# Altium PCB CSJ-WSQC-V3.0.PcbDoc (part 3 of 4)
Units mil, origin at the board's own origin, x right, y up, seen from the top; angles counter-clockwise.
Board outline 5060 x 7131.55 mil, 4 copper layers (Top Layer, InternalPlane1, InternalPlane2, Bottom Layer); 390 components, 277 nets, 1183 pads, 601 vias.
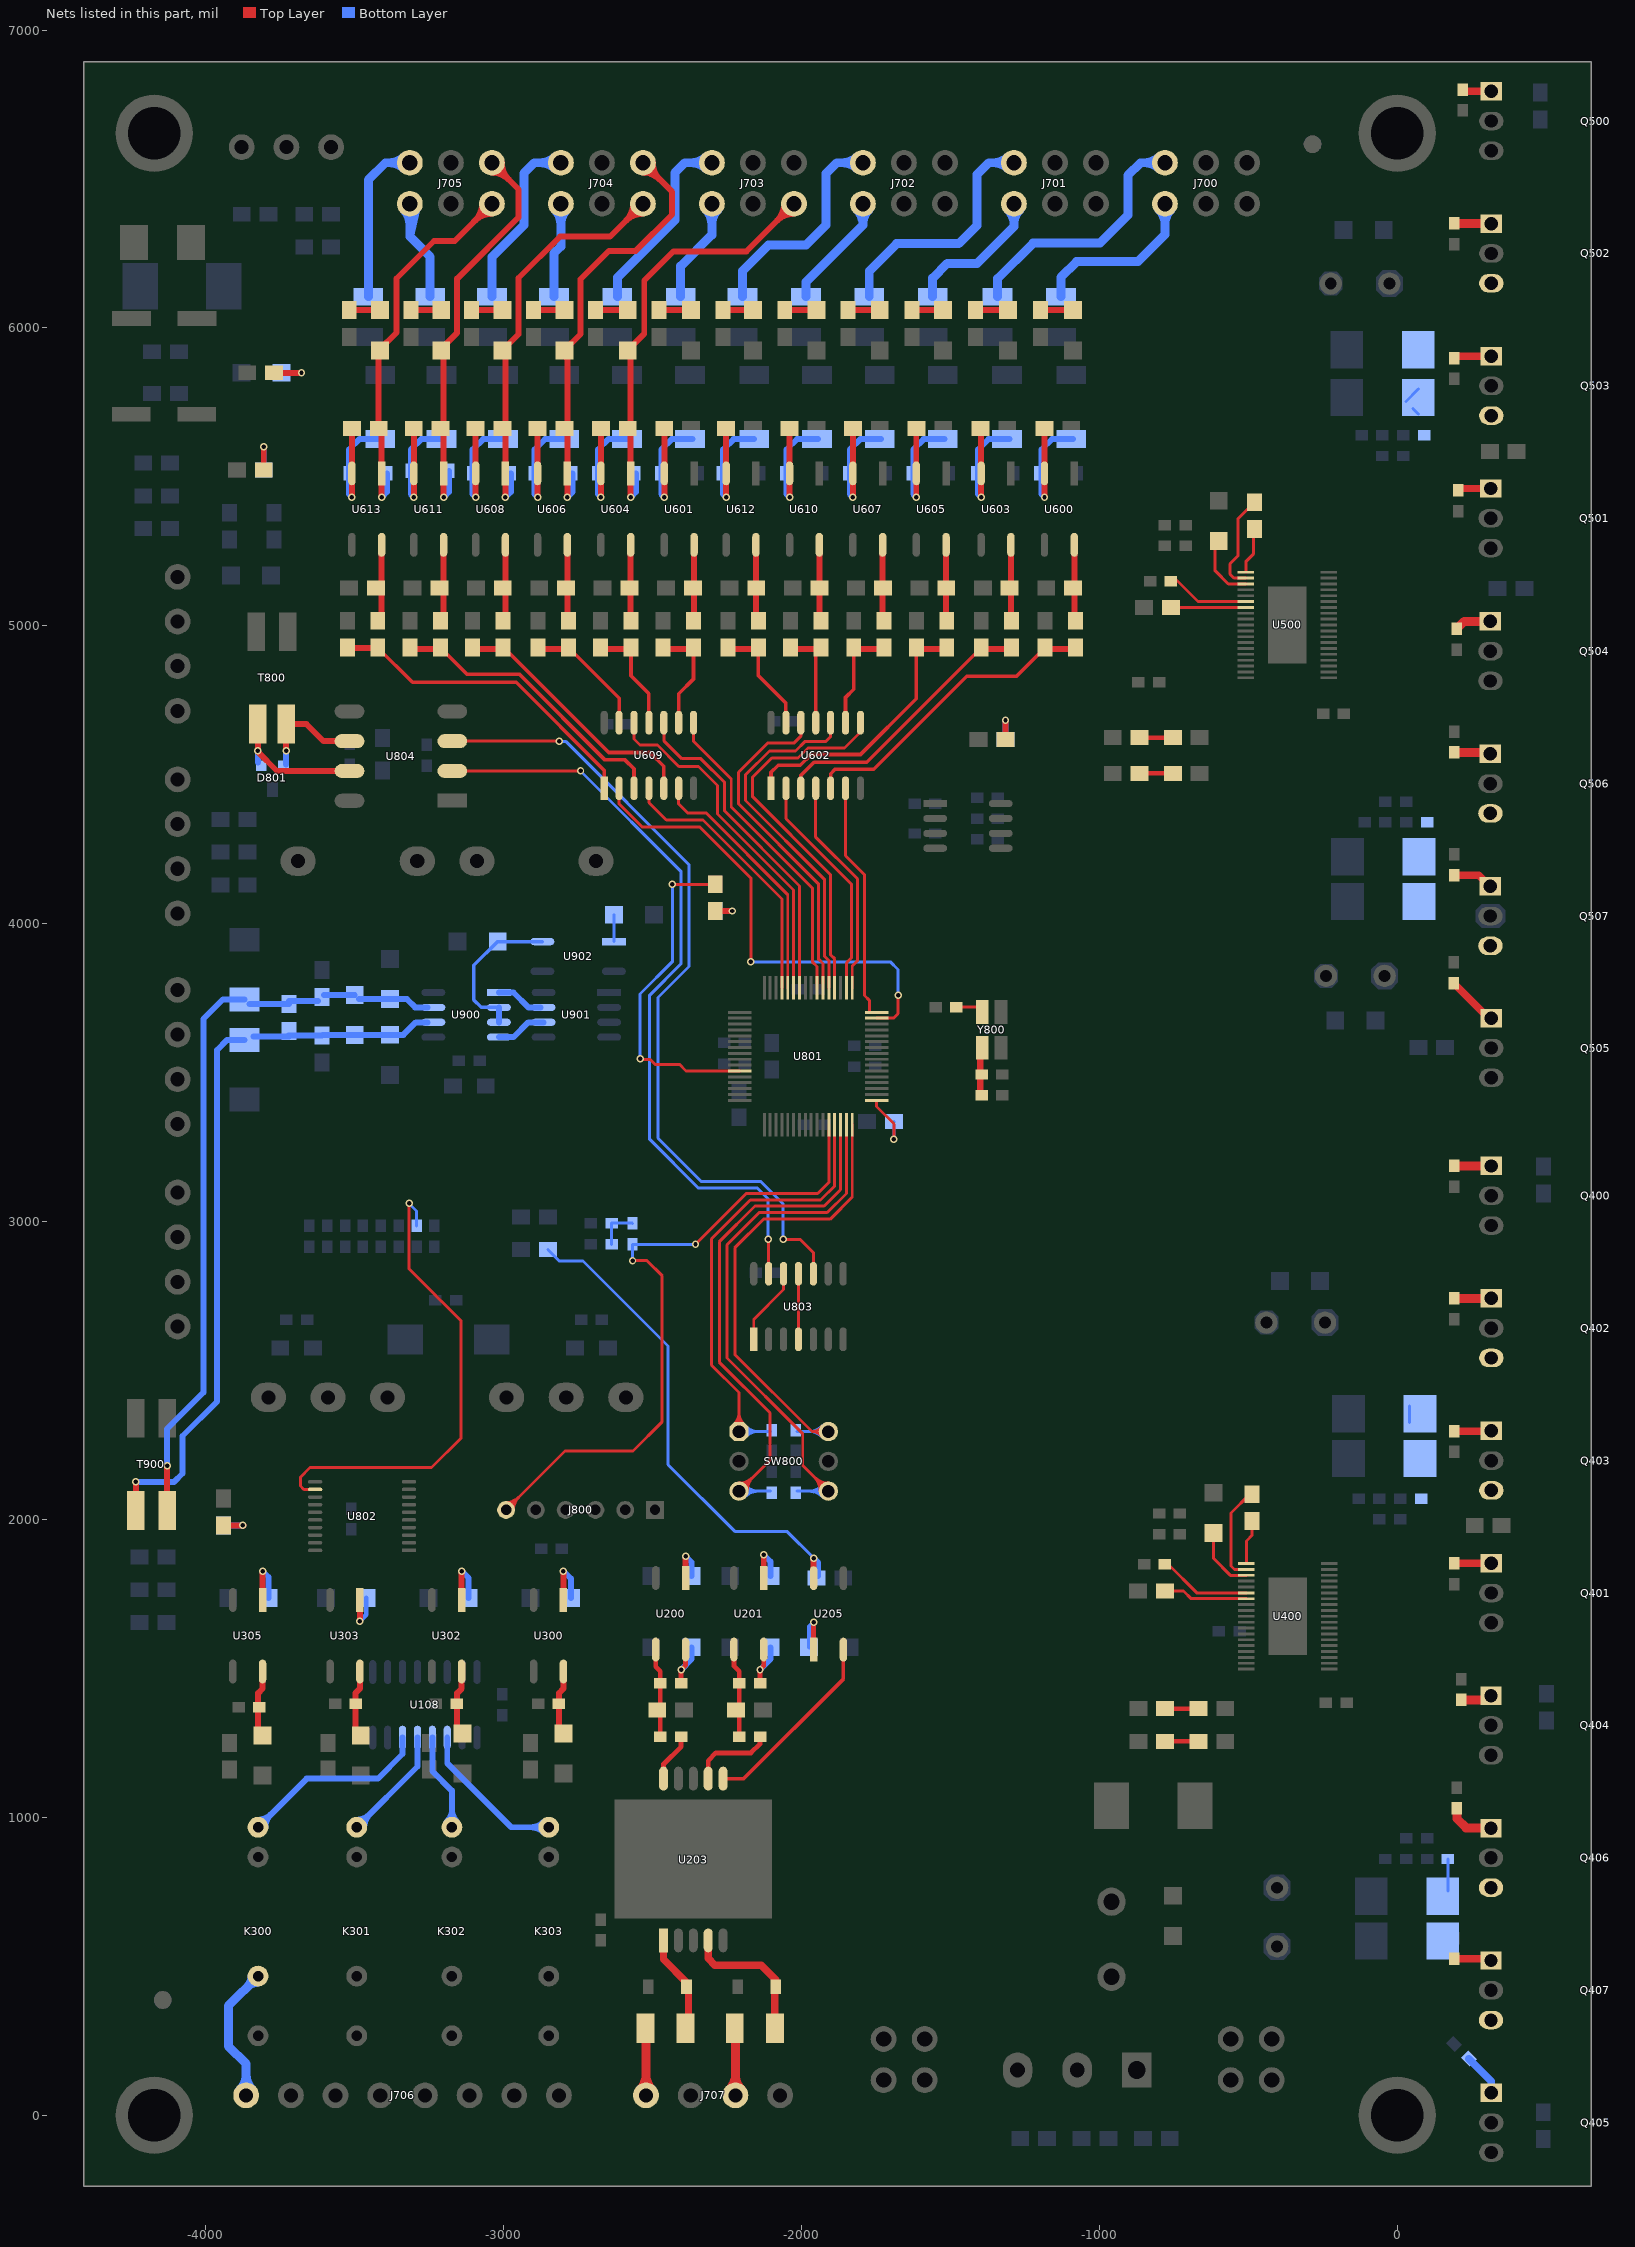
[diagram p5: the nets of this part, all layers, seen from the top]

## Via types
v1: diameter 25, hole 15, Top Layer to Bottom Layer, 303 vias
v2: diameter 25, hole 12, Top Layer to Bottom Layer, 94 vias
v3: diameter 50, hole 25, Top Layer to Bottom Layer, 71 vias
v4: diameter 30, hole 16, Top Layer to Bottom Layer, 71 vias
v5: diameter 12, hole 8, Top Layer to Bottom Layer, 25 vias
v6: diameter 25, hole 12, Top Layer to Bottom Layer, tented both sides, 24 vias
v7: diameter 35, hole 20, Top Layer to Bottom Layer, 7 vias
v8: diameter 20, hole 12, Top Layer to Bottom Layer, 3 vias
v9: diameter 8, hole 5, Top Layer to Bottom Layer, 2 vias
v10: diameter 35, hole 25, Top Layer to Bottom Layer, 1 vias

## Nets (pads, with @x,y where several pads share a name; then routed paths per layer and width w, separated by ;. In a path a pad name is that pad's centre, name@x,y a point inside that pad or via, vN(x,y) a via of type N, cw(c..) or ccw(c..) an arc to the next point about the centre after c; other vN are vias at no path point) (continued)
IN8: D607.2 J703.4 R613.1 R617.1 U604.1 | length 1708
  Top Layer w20: R617.1@-2583.54,5661.73 R617.1@-2573.54,5651.73 ; v1(-2573.54,5431.73) U604.1@-2573.54,5511.73 -2573.54,5914.73 R613.1@-2583.54,5924.73 -2528,5980.27 -2528,6159.35 -2430.62,6256.73 -2185.45,6256.73 J703.4@-2025.45,6416.73 ; J703.4@-2058.76,6416.73 cw(c-2139.17,6416.73) -2082.31,6359.87 ; -2082.31,6359.87 cw(c-2025.45,6303.02) -2025.45,6383.43 J703.4@-2025.45,6416.73 ; -2082.31,6359.87 J703.4@-2025.45,6416.73
  Bottom Layer w20: v1(-2573.54,5431.73) -2555.59,5449.69 -2555.59,5511.73 D607.2@-2558.08,5511.73
IN9: D611.2 J704.1 R623.1 R627.1 U606.1 | length 1713.6
  Top Layer w20: R627.1@-2796.27,5661.73 R627.1@-2786.27,5651.73 ; v1(-2786.27,5431.73) U606.1@-2786.27,5511.73 -2786.27,5896 -2796.27,5906 R623.1@-2796.27,5924.73 -2742,5979 -2742,6163.35 -2646.62,6258.73 -2556.62,6258.73 -2434.45,6380.91 -2434.45,6456.53 J704.1@-2532.45,6554.53 ; J704.1@-2532.45,6521.22 cw(c-2532.45,6440.81) -2475.59,6497.67 ; J704.1@-2532.45,6554.53 -2499.14,6554.53 ccw(c-2418.73,6554.53) -2475.59,6497.67 ; J704.1@-2532.45,6554.53 -2475.59,6497.67
  Bottom Layer w20: v1(-2786.27,5431.73) -2768.31,5449.69 -2768.31,5511.73 D611.2@-2770.19,5511.73
IN10: D615.2 J704.4 R633.1 R637.1 U608.1 | length 1625.8
  Top Layer w20: R637.1@-3003.99,5661.73 R637.1@-2993.99,5651.73 ; v1(-2993.99,5431.73) U608.1@-2993.99,5511.73 -2993.99,5914.73 R633.1@-3003.99,5924.73 -2950,5978.73 -2950,6167.35 -2810.62,6306.73 -2642.45,6306.73 J704.4@-2532.45,6416.73 ; J704.4@-2565.76,6416.73 cw(c-2646.17,6416.73) -2589.31,6359.87 ; -2589.31,6359.87 cw(c-2532.45,6303.02) -2532.45,6383.43 J704.4@-2532.45,6416.73 ; -2589.31,6359.87 J704.4@-2532.45,6416.73
  Bottom Layer w20: v1(-2993.99,5431.73) -2976.04,5449.69 -2976.04,5511.73 D615.2@-2977.29,5511.73
IN11: D619.2 J705.1 R643.1 R647.1 U611.1 | length 1618.8
  Top Layer w20: R647.1@-3211.72,5661.73 R647.1@-3201.72,5651.73 ; v1(-3201.72,5431.73) U611.1@-3201.72,5511.73 -3201.72,5746 -3201.72,5925.72 -3207.59,5931.59 -3156,5983.18 -3156,6165.35 -2950,6371.35 -2950,6465.08 J705.1@-3039.45,6554.53 ; J705.1@-3039.45,6521.22 cw(c-3039.45,6440.81) -2982.59,6497.67 ; J705.1@-3039.45,6554.53 -3006.14,6554.53 ccw(c-2925.73,6554.53) -2982.59,6497.67 ; J705.1@-3039.45,6554.53 -2982.59,6497.67
  Bottom Layer w20: v1(-3201.72,5431.73) -3183.77,5449.69 D619.2@-3183.77,5520
IN12: D623.2 J705.4 R653.1 R657.1 U613.1 | length 1471.5
  Top Layer w20: R657.1@-3419.45,5651.73 R657.1@-3419.45,5661.73 ; v1(-3409.45,5431.73) U613.1@-3409.45,5511.73 -3409.45,5651.73 R657.1@-3419.45,5661.73 ; J705.4@-3072.76,6416.73 cw(c-3153.17,6416.73) -3096.31,6359.87 cw(c-3039.45,6303.01) -3039.45,6383.42 J705.4@-3039.45,6416.73 ; J705.4@-3047.36,6424.64 -3039.45,6432.55 J705.4@-3039.45,6416.73 ; R657.1@-3419.45,5661.73 -3419.45,5924.73 -3360,5984.18 -3360,6166 -3234,6292 -3164.18,6292 J705.4@-3039.45,6416.73
  Bottom Layer w20: v1(-3409.45,5431.73) -3391.49,5449.69 D623.2@-3391.49,5511.73
INPUT1: U602.6 U801.48 | length 812.2
  Top Layer w10: U602.6@-1852.45,4454.73 -1852.45,4228.45 -1788.62,4164.62 -1788.62,4018.73 ; -1788.62,4025.91 -1788.62,4018.73 ; U801.48@-1753.04,3702.37 -1772.62,3702.37 -1772.62,3742.73 -1788.62,3758.73 -1788.62,4018.73
INPUT2: U602.4 U801.49 | length 749.8
  Top Layer w10: U602.4@-1952.45,4454.73 -1952.45,4290.45 -1812.45,4150.45 -1812.45,4000.73 ; U801.49@-1829.81,3784.14 -1829.81,3858.19 -1812.45,3875.55 -1812.45,4000.73 ; -1812.45,4014.73 -1812.45,4000.73
INPUT3: U602.2 U801.50 | length 810.8
  Top Layer w10: U602.2@-2052.45,4419.73 U602.2@-2052.45,4454.73 -2052.45,4352.45 -1832.45,4132.45 -1832.45,3992.73 ; U801.50@-1849.5,3784.14 -1849.5,3868.5 -1832.45,3885.55 -1832.45,3992.73 ; -1832.45,3999.73 -1832.45,3992.73
INPUT4: U602.8 U801.52 | length 1277.3
  Top Layer w10: U801.52@-1888.87,3784.14 -1888.87,3881.98 -1902.45,3895.56 -1902.45,4164.45 -2164,4426 -2164,4492 -2100,4556 -2012,4556 -1978,4590 -1856,4590 -1802.45,4643.55 U602.8@-1802.45,4674.73
INPUT5: U602.10 U801.53 | length 1217.2
  Top Layer w10: U801.53@-1908.55,3784.14 -1908.55,3876.21 -1922.45,3890.1 -1922.45,4147.73 -2188,4413.28 -2188,4500 -2108,4580 -2020,4580 -1988,4612 -1918,4612 -1902.45,4627.55 U602.10@-1902.45,4674.73
INPUT6: U602.12 U801.54 | length 1146.5
  Top Layer w10: U602.12@-2002.45,4674.73 -2002.45,4629.55 -2026,4606 -2114,4606 -2212,4508 -2212,4402.28 -1942.45,4132.73 -1942.45,3880.56 -1928.24,3866.35 U801.54@-1928.24,3784.14
INPUT7: U609.8 U801.55 | length 1062.3
  Top Layer w10: U609.8@-2362.45,4674.73 -2362.45,4612.45 -2236,4486 -2236,4391.28 -1962.45,4117.73 -1962.45,3870.56 -1947.92,3856.03 U801.55@-1947.92,3784.14
INPUT8: U609.10 U801.58 | length 1117.1
  Top Layer w10: U609.10@-2462.45,4674.73 -2462.45,4614.45 -2402,4554 -2338,4554 -2258,4474 -2258,4378.28 -2006.59,4126.87 -2006.59,4072 -2006.98,4071.61 U801.58@-2006.98,3784.14
INPUT9: U609.12 U801.59 | length 1185.6
  Top Layer w10: U609.12@-2562.45,4674.73 -2562.45,4619.73 -2542.45,4599.73 -2483.73,4599.73 -2412,4528 -2346,4528 -2282,4464 -2282,4368 -2026.66,4112.66 U801.59@-2026.66,3784.14
INPUT10: U609.6 U801.60 | length 858.2
  Top Layer w10: U609.6@-2412.45,4454.73 -2412.45,4401.9 -2382.54,4372 -2321.08,4372 -2046.35,4097.27 U801.60@-2046.35,3784.14
INPUT11: U609.4 U801.61 | length 927.5
  Top Layer w10: U609.4@-2512.45,4454.73 -2512,4454.28 -2512,4406 -2454,4348 -2331.08,4348 -2066.03,4082.95 U801.61@-2066.03,3784.14
INPUT12: U609.2 U801.47 | length 1660.4
  Top Layer w10: -2612.45,4410.45 U609.2@-2612.45,4454.73 -2612.45,4402.45 -2534,4324 -2341.08,4324 -2170,4152.92 v1(-2170,3872) ; U801.47@-1748.04,3682.69 -1691.31,3682.69 -1676,3698 v1@-1676,3766
  Bottom Layer w10: v1(-2170,3872) -1702,3872 -1676,3846 v1(-1676,3760)
M\C\L\R\: J800.6 R809.2 U801.28 | length 2402.7
  Top Layer w10: J800.6@-2992,2032 -2794,2230 -2566,2230 -2468,2328 -2468,2818 -2518.55,2868.55 v1(-2567.45,2868.55) ; J800.6@-2992,2047 ccw(c-2992,2083.21) -2966.39,2057.61 ccw(c-2940.79,2032) J800.6@-2977,2032 ; J800.6@-2992,2057 ccw(c-2992,2117.36) -2949.32,2074.68 ccw(c-2906.64,2032) J800.6@-2967,2032 ; v1(-2356,2923.73) -2185.73,3094 -1946,3094 -1908.55,3131.45 U801.28@-1908.55,3325.32
  Bottom Layer w10: v1(-2567.45,2868.55) R809.2@-2567.45,2923.73 v1(-2356,2923.73)
NetC200_1: C200.1 R200.2 U200.4 | length 208.5
  Top Layer w16: C200.1@-2404.45,1450.73 v1(-2404.45,1495.73) -2389.45,1510.73 U200.4@-2389.45,1563.53
  Bottom Layer w20: v1(-2404.45,1495.73) -2369.45,1530.73 R200.2@-2369.45,1570.73
NetC200_2: C200.2 R202.1 R203.2 U200.3 | length 299
  Top Layer w16: U200.3@-2489.45,1563.53 -2489.45,1505.73 -2474.45,1490.73 C200.2@-2474.45,1450.73 -2474.45,1360.73 R202.1@-2474.45,1270.73
NetC202_1: C202.1 R204.2 U201.4 | length 207.5
  Top Layer w16: C202.1@-2139.45,1450.73 v1(-2139.45,1495.73) -2126.95,1508.23 U201.4@-2126.95,1563.53
  Bottom Layer w20: v1(-2139.45,1495.73) -2104.45,1530.73 R204.2@-2104.45,1570.73
NetC202_2: C202.2 R206.1 R207.2 U201.3 | length 307.1
  Top Layer w16: U201.3@-2226.95,1563.53 -2226.95,1508.23 -2209.45,1490.73 -2209.45,1455.73 -2206.95,1453.23 -2204.45,1450.73 C202.2@-2209.45,1450.73 -2209.45,1360.73 R206.1@-2209.45,1270.73
NetC300_1: C300.1 R300.2 U300.4 | length 220.2
  Top Layer w20: R300.2@-2799.45,1281.73 -2814.45,1296.73 C300.1@-2814.45,1381.73 -2814.45,1416.73 -2799.45,1431.73 U300.4@-2799.45,1489.53
NetC302_1: C302.1 R305.2 U302.4 | length 220.2
  Top Layer w20: R305.2@-3141.11,1281.73 -3156.11,1296.73 -3156.11,1381.73 -3156.11,1416.73 -3141.11,1431.73 U302.4@-3141.11,1489.53
NetC303_1: C303.1 R313.2 U303.4 | length 220.2
  Top Layer w20: R313.2@-3482.78,1281.73 -3497.78,1296.73 -3497.78,1381.73 -3497.78,1416.73 -3482.78,1431.73 U303.4@-3482.78,1489.53
NetC305_1: C305.1 R319.2 U305.4 | length 220.2
  Top Layer w20: R319.2@-3809.45,1281.73 -3824.45,1296.73 -3824.45,1381.73 -3824.45,1416.73 -3809.45,1431.73 U305.4@-3809.45,1489.53
NetC406_1: C406.1 U400.1 | length 150.8
  Top Layer w10: U400.1@-506.62,1851.9 -506.62,1927.38 -487.45,1946.55 C406.1@-487.45,1994.73
NetC406_2: C406.2 U400.2 | length 330.8
  Top Layer w10: U400.2@-506.62,1832.21 -546.21,1832.21 -558,1844 -558,2022 -495.27,2084.73 C406.2@-487.45,2084.73
NetC407_1: C407.1 U400.3 | length 223.8
  Top Layer w10: C407.1@-607.45,1954.73 -617.45,1944.73 -617.45,1869.45 -560.53,1812.53 U400.3@-506.62,1812.53
NetC408_1: C408.1 U400.6 | length 313.4
  Top Layer w10: C408.1@-780,1850 -770,1850 -673.47,1753.47 U400.6@-506.62,1753.47
NetC409_1: C409.1 U400.7 | length 284.2
  Top Layer w10: C409.1@-780,1760 -718,1760 -691.79,1733.79 U400.7@-506.62,1733.79
NetC506_1: C506.1 U500.1 | length 171.1
  Top Layer w10: U500.1@-508.62,5179.9 -508.62,5215.38 -482,5242 -482,5322.18 C506.1@-469.45,5334.73
NetC506_2: C506.2 U500.2 | length 348.6
  Top Layer w10: U500.2@-508.62,5160.21 -548.93,5160.21 -562,5173.28 -562,5208 -535.45,5234.55 -535.45,5358.73 C506.2@-469.45,5424.73
NetC507_1: C507.1 U500.3 | length 204.4
  Top Layer w10: C507.1@-619.45,5264.73 -611.45,5256.73 -611.45,5184.73 -567.24,5140.53 U500.3@-508.62,5140.53
NetC508_1: C508.1 U500.6 | length 260.6
  Top Layer w10: C508.1@-740,5152 -669.47,5081.47 U500.6@-508.62,5081.47
NetC509_1: C509.1 U500.7 | length 251.5
  Top Layer w10: C509.1@-760,5062 -660.21,5062 -660,5061.79 U500.7@-508.62,5061.79
NetC600_2: C600.2 R604.2 U602.5 | length 1041.5
  Top Layer w10: C600.2@-1182.62,4919.38 C600.2@-1182.62,4926.73
  Top Layer w12: U602.5@-1902.45,4454.73 -1902.45,4503.55 -1888,4518 -1758,4518 -1445,4831 -1278.35,4831 C600.2@-1182.62,4926.73
  Top Layer w20: C600.2@-1170.79,4922.73 R604.2@-1080.62,4922.73
NetC601_2: C601.2 R605.2 U609.9 | length 379.4
  Top Layer w12: C601.2@-2458.62,4921.73 C601.2@-2458.62,4926.73 ; U609.9@-2412.45,4670.73 U609.9@-2412.45,4674.73 -2412.45,4771.55 -2362.62,4821.38 -2362.62,4921.73 R605.2@-2362.62,4926.73
  Top Layer w20: C601.2@-2458.62,4921.73 -2362.62,4921.73 R605.2@-2360.81,4921.73
NetC602_2: C602.2 R614.2 U602.3 | length 939.8
  Top Layer w10: C602.2@-1396.62,4923.38 C602.2@-1396.62,4926.73
  Top Layer w12: U602.3@-2002.45,4454.73 -2002.45,4497.55 -1958,4542 -1781.35,4542 C602.2@-1396.62,4926.73 ; C602.2@-1388.62,4922.73 C602.2@-1388.62,4926.73 ; R614.2@-1294.62,4922.73 R614.2@-1294.62,4926.73
  Top Layer w20: C602.2@-1388.62,4922.73 -1294.62,4922.73 R614.2@-1286.62,4922.73
NetC603_2: C603.2 R615.2 U609.11 | length 376
  Top Layer w12: R615.2@-2572.62,4926.73 -2572.62,4832.62 -2512.45,4772.45 U609.11@-2512.45,4674.73
  Top Layer w20: C603.2@-2672.62,4921.73 R615.2@-2573.54,4921.73
NetC604_2: C604.2 R624.2 U602.1 | length 899.9
  Top Layer w12: U602.1@-2102.45,4454.73 -2102.45,4508 -2078.45,4532 -2004,4532 -1968,4568 -1802,4568 -1614.62,4755.38 C604.2@-1614.62,4926.73
  Top Layer w20: C604.2@-1599.9,4921.73 R624.2@-1514.9,4921.73
NetC605_2: C605.2 R625.2 U609.13 | length 428.5
  Top Layer w12: C605.2@-2878.62,4922.73 C605.2@-2878.62,4926.73 ; R625.2@-2782.62,4926.73 -2778.62,4922.73 -2612.45,4756.56 U609.13@-2612.45,4674.73
  Top Layer w20: C605.2@-2878.62,4922.73 -2778.62,4922.73 R625.2@-2776.62,4922.73
NetC606_2: C606.2 R634.2 U602.9 | length 348.5
  Top Layer w12: U602.9@-1852.45,4674.73 -1852.45,4759.55 -1824.62,4787.38 -1824.62,4864.73 C606.2@-1824.62,4926.73
  Top Layer w20: C606.2@-1812.63,4921.73 -1728.62,4921.73 R634.2@-1727.63,4921.73
NetC607_2: C607.2 R635.2 U609.5 | length 870.3
  Top Layer w12: R635.2@-2998.73,4926.73 -2646.73,4574.73 -2508.73,4574.73 -2462.45,4528.45 U609.5@-2462.45,4454.73
  Top Layer w20: C607.2@-3103.99,4921.73 R635.2@-3008.62,4921.73
NetC608_2: C608.2 R644.2 U602.11 | length 349
  Top Layer w10: R644.2@-1952.45,4909.64 R644.2@-1940.36,4921.73
  Top Layer w12: C608.2@-2036.62,4921.73 C608.2@-2036.62,4926.73 ; U602.11@-1952.45,4674.73 R644.2@-1952.45,4909.64
  Top Layer w20: C608.2@-2043.62,4921.73 C608.2@-2036.62,4921.73 ; C608.2@-2025.36,4921.73 R644.2@-1940.36,4921.73
NetC609_2: C609.2 R645.2 U609.3 | length 999.1
  Top Layer w10: R645.2@-3212.62,4926.73 R645.2@-3208.62,4922.73
  Top Layer w12: C609.2@-3316,4915.35 -3308.62,4922.73 C609.2@-3308.62,4926.73 ; R645.2@-3208.62,4922.73 -3123.89,4838 -2948,4838 -2659.73,4549.73 -2592.45,4549.73 -2562.45,4519.73 U609.3@-2562.45,4454.73
  Top Layer w20: C609.2@-3308.62,4922.73 -3208.62,4922.73 R645.2@-3207.72,4922.73
NetC610_2: C610.2 R654.2 U602.13 | length 354.9
  Top Layer w12: C610.2@-2238.62,4921.73 C610.2@-2238.62,4926.73 ; R654.2@-2145.08,4926.73 -2145.08,4921.73 -2145.08,4833.08 -2052.45,4740.45 U602.13@-2052.45,4714.73
  Top Layer w20: C610.2@-2238.62,4921.73 -2145.08,4921.73 R654.2@-2139.08,4921.73
NetC611_2: C611.2 R655.2 U609.1 | length 1126.2
  Top Layer w10: R655.2@-3422.62,4922.62 R655.2@-3422.62,4926.73
  Top Layer w12: R655.2@-3428.62,4924.73 R655.2@-3428.62,4926.73 ; R655.2@-3407.45,4911.56 R655.2@-3422.62,4926.73 -3305.89,4810 -2958,4810 -2662.45,4514.45 U609.1@-2662.45,4454.73
  Top Layer w20: C611.2@-3536.62,4924.73 R655.2@-3428.62,4924.73
NetC801_1: C801.1 R806.1 R809.1 | length 142.8
  Bottom Layer w10: R806.1@-2637.45,2923.73 C801.1@-2637.45,2993.73 -2637.45,2995.73 -2569.45,2995.73 R809.1@-2567.45,2993.73
NetC803_1: C803.1 L800.2 Y800.4 | length 337.7
  Top Layer w10: C803.1@-1405.44,3422 -1405.44,3493.73 -1405.44,3583.73 Y800.4@-1405.44,3601.73
  Top Layer w12: C803.1@-1395.45,3423.73 L800.2@-1395.45,3493.73 Y800.4@-1395.45,3581.72
NetC804_1: C804.1 U801.33 | length 215.1
  Top Layer w10: U801.33@-1748.04,3407.09 -1748.04,3386.04 -1690,3328 v1(-1690,3276)
  Bottom Layer w10: v1(-1690,3276) C804.1@-1690,3336
NetC900_2: C900.2 C901.1 D900.2 R900.1 R902.2 T900.2 U900.6 | length 2443.1
  Top Layer w20: T900.2@-4235,2030 v1(-4235,2126) v1@-4235,2128
  Bottom Layer w20: v1(-4235,2126) -4106,2126 -4078,2154 -4078,2280 -3962,2396 -3962,3576 -3928,3610 D900.2@-3870,3610 ; D900.2@-3840,3622 C901.1@-3720,3622 ; C901.1@-3722,3624 C900.2@-3610,3624 ; C900.2@-3608,3626 R900.1@-3500,3626 ; R900.1@-3499,3627 R902.2@-3382,3627 -3337,3627 -3295,3669 U900.6@-3256,3669
NetC901_2: C901.2 C902.2 D901.2 R900.2 R903.2 T900.1 U900.7 | length 2440.5
  Top Layer w20: T900.1@-4130,2030 v1(-4130,2180)
  Bottom Layer w20: v1(-4130,2180) -4130,2304 -4008,2426 -4008,3680 -3942,3746 D901.2@-3870,3746 ; D901.2@-3854,3730 C901.2@-3720,3730 ; C901.2@-3720,3740 C902.2@-3624,3740 ; C902.2@-3603,3761 R900.2@-3500,3761 ; R900.2@-3486,3747 R903.2@-3382,3747 -3325,3747 -3297,3719 U900.7@-3256,3719
NetD101_2: D101.2 R100.1 | length 156.4
  Top Layer w20: D101.2@-3805.38,5522.44 v1(-3805.38,5600.62)
  Bottom Layer w20: R100.1@-3805.38,5522.44 v1(-3805.38,5600.62)
NetD102_2: D102.2 R101.1 | length 130
  Top Layer w20: D102.2@-1315.38,4618.44 v1(-1315.38,4683.44)
  Bottom Layer w20: R101.1@-1315.38,4618.44 v1(-1315.38,4683.44)
NetD103_2: D103.2 R102.1 | length 159
  Top Layer w20: D103.2@-3770.73,5849.38 v1(-3678.73,5849.38)
  Bottom Layer w20: R102.1@-3745.73,5849.38 v1(-3678.73,5849.38)
NetD105_2: D105.2 R115.1 | length 128
  Top Layer w20: D105.2@-3938,1980 v1@-3874,1980
  Bottom Layer w20: R115.1@-3940,1980 v1(-3876,1980)
NetD200_2: D200.2 R208.2 U203.1 | length 316.9
  Top Layer w25: U203.1@-2463.45,586.73 -2463.45,569.73 -2463.45,523.45 -2386.49,446.49 D200.2@-2386.49,431.73 ; R208.2@-2379.45,301.73 D200.2@-2379.45,431.73
NetD201_2: D201.2 R209.2 U203.4 | length 480
  Top Layer w25: U203.4@-2313.45,586.73 -2313.45,526.73 -2290.72,504 -2135.45,504 -2086.49,455.05 D201.2@-2086.49,431.73 ; R209.2@-2089.45,291.73 D201.2@-2089.45,431.73
NetD400_2: D400.2 R410.2 | length 100
  Top Layer w15: D400.2@-779.45,1364.73 R410.2@-679.45,1364.73
NetD401_2: D401.2 R409.2 | length 100
  Top Layer w15: D401.2@-779.45,1254.73 R409.2@-679.45,1254.73
NetD500_2: D500.2 R510.2 | length 100
  Top Layer w15: D500.2@-865.45,4504.73 R510.2@-765.45,4504.73
NetD501_2: D501.2 R509.2 | length 100
  Top Layer w15: D501.2@-865.45,4624.73 R509.2@-765.45,4624.73
NetD600_1: D600.1 R602.2 | length 95
  Top Layer w20: D600.1@-1189.45,6059.73 R602.2@-1094.45,6059.73
NetD601_1: D601.1 R603.2 | length 93.6
  Top Layer w20: D601.1@-2464.45,6059.73 R603.2@-2370.81,6059.73
NetD602_1: D602.1 R606.2 R608.1 U600.2 | length 513.6
  Top Layer w20: v1(-1184.45,5431.73) U600.2@-1184.45,5511.73 R606.2@-1184.45,5661.73
  Bottom Layer w20: v1(-1184.45,5431.73) -1194.45,5441.73 -1194.45,5511.73 -1194.45,5591.73 -1159.45,5626.73 R608.1@-1094.45,5626.73 R608.1@-1089.45,5626.73
NetD603_1: D603.1 R607.2 R609.1 U601.2 | length 513.6
  Top Layer w20: v1(-2460.81,5431.73) U601.2@-2460.81,5511.73 R607.2@-2460.81,5661.73
  Bottom Layer w20: v1(-2460.81,5431.73) -2470.81,5441.73 -2470.81,5511.73 -2470.81,5591.73 -2435.81,5626.73 R609.1@-2374.9,5626.73 R609.1@-2365.81,5626.73
NetD604_1: D604.1 R612.2 | length 97.3
  Top Layer w20: D604.1@-1404.45,6059.73 R612.2@-1307.18,6059.73
NetD605_1: D605.1 R613.2 | length 95.9
  Top Layer w20: D605.1@-2679.45,6059.73 R613.2@-2583.54,6059.73
NetD606_1: D606.1 R616.2 R618.1 U603.2 | length 515.9
  Top Layer w20: R616.2@-1399.45,5661.73 -1397.18,5661.73 U603.2@-1397.18,5511.73 v1(-1397.18,5431.73)
  Bottom Layer w20: v1(-1397.18,5431.73) -1407.18,5441.73 -1407.18,5511.73 -1407.18,5591.73 -1372.18,5626.73 R618.1@-1310.36,5626.73 R618.1@-1302.18,5626.73
NetD607_1: D607.1 R617.2 R619.1 U604.2 | length 513.6
  Top Layer w20: v1(-2673.54,5431.73) U604.2@-2673.54,5511.73 R617.2@-2673.54,5661.73
  Bottom Layer w20: v1(-2673.54,5431.73) -2683.54,5441.73 -2683.54,5511.73 -2683.54,5591.73 -2648.54,5626.73 R619.1@-2585.81,5626.73 R619.1@-2578.54,5626.73
NetD608_1: D608.1 R622.2 | length 94.5
  Top Layer w20: D608.1@-1619.45,6059.73 R622.2@-1524.9,6059.73
NetD609_1: D609.1 R623.2 | length 93.2
  Top Layer w20: D609.1@-2889.45,6059.73 R623.2@-2796.27,6059.73
NetD610_1: D610.1 R626.2 R628.1 U605.2 | length 514.1
  Top Layer w20: v1(-1614.9,5431.73) U605.2@-1614.9,5511.73 -1614.9,5661.73 R626.2@-1614.45,5661.73
  Bottom Layer w20: v1(-1614.9,5431.73) -1624.9,5441.73 -1624.9,5511.73 -1624.9,5591.73 -1589.9,5626.73 R628.1@-1526.27,5626.73 R628.1@-1519.9,5626.73
NetD611_1: D611.1 R627.2 R629.1 U606.2 | length 513.6
  Top Layer w20: v1(-2886.27,5431.73) U606.2@-2886.27,5511.73 R627.2@-2886.27,5661.73
  Bottom Layer w20: v1(-2886.27,5431.73) -2896.27,5441.73 -2896.27,5511.73 -2896.27,5591.73 -2861.27,5626.73 R629.1@-2796.72,5626.73 R629.1@-2791.27,5626.73
NetD612_1: D612.1 R632.2 | length 96.8
  Top Layer w20: D612.1@-1834.45,6059.73 R632.2@-1737.63,6059.73
NetD613_1: D613.1 R633.2 | length 95.5
  Top Layer w20: D613.1@-3099.45,6059.73 R633.2@-3003.99,6059.73
NetD614_1: D614.1 R636.2 R638.1 U607.2 | length 513.6
  Top Layer w20: v1(-1827.63,5431.73) U607.2@-1827.63,5511.73 R636.2@-1827.63,5661.73
  Bottom Layer w20: v1(-1827.63,5431.73) -1837.63,5441.73 -1837.63,5511.73 -1837.63,5591.73 -1802.63,5626.73 R638.1@-1737.18,5626.73 R638.1@-1732.63,5626.73
NetD615_1: D615.1 R637.2 R639.1 U608.2 | length 513.6
  Top Layer w20: v1(-3093.99,5431.73) U608.2@-3093.99,5511.73 R637.2@-3093.99,5661.73
  Bottom Layer w20: v1(-3093.99,5431.73) -3103.99,5441.73 -3103.99,5511.73 -3103.99,5591.73 -3068.99,5626.73 R639.1@-3002.63,5626.73 R639.1@-2998.99,5626.73
NetD616_1: D616.1 R642.2 | length 94.1
  Top Layer w20: D616.1@-2044.45,6059.73 R642.2@-1950.36,6059.73
NetD617_1: D617.1 R643.2 | length 92.7
  Top Layer w20: D617.1@-3304.45,6059.73 R643.2@-3211.72,6059.73
NetD618_1: D618.1 R646.2 R648.1 U610.2 | length 513.6
  Top Layer w20: v1(-2040.36,5431.73) U610.2@-2040.36,5511.73 R646.2@-2040.36,5661.73
  Bottom Layer w20: v1(-2040.36,5431.73) -2050.36,5441.73 -2050.36,5511.73 -2050.36,5591.73 -2015.36,5626.73 R648.1@-1948.08,5626.73 R648.1@-1945.36,5626.73
NetD619_1: D619.1 R647.2 R649.1 U611.2 | length 511.8
  Top Layer w20: v1(-3301.72,5431.73) U611.2@-3301.72,5511.73 R647.2@-3301.72,5661.73
  Bottom Layer w20: v1(-3301.72,5431.73) -3311.72,5441.73 -3311.72,5570 -3311.72,5591.73 -3276.72,5626.73 R649.1@-3208.54,5626.73
NetD620_1: D620.1 R652.2 | length 96.4
  Top Layer w20: D620.1@-2259.45,6059.73 R652.2@-2163.08,6059.73
NetD621_1: D621.1 R653.2 | length 95
  Top Layer w20: D621.1@-3514.45,6059.73 R653.2@-3419.45,6059.73
NetD622_1: D622.1 R656.2 R658.1 U612.2 | length 512.7
  Top Layer w20: v1(-2253.08,5431.73) U612.2@-2253.08,5511.73 R656.2@-2253.08,5661.73
  Bottom Layer w20: v1(-2253.08,5431.73) -2263.08,5441.73 -2263.08,5511.73 -2263.08,5591.73 -2228.08,5626.73 R658.1@-2158.99,5626.73
NetD623_1: D623.1 R657.2 R659.1 U613.2 | length 513.6
  Top Layer w20: v1(-3509.45,5431.73) U613.2@-3509.45,5511.73 R657.2@-3509.45,5661.73
  Bottom Layer w20: v1(-3509.45,5431.73) -3519.45,5441.73 D623.1@-3519.45,5511.73 -3519.45,5591.73 -3484.45,5626.73 R659.1@-3414.45,5626.73
NetD800_1: D800.1 R810.1 | length 115.5
  Top Layer w20: D800.1@-2289.73,4042.55 v1(-2232,4042.55)
  Bottom Layer w20: R810.1@-2289.73,4042.55 v1(-2232,4042.55)
NetD800_2: D800.2 U801.11 | length 1121.8
  Top Layer w10: v1@-2540,3548 -2540,3544 -2508,3544 -2492,3528 -2410,3528 -2387.52,3505.52 U801.11@-2206.86,3505.52 ; v1(-2434,4132) D800.2@-2296,4132
  Bottom Layer w10: v1(-2542,3546) -2542,3764 -2434,3872 v1(-2434,4132)
NetD801_1: D801.1 T800.2 U804.7 | length 466.2
  Top Layer w20: T800.2@-3825,4670 v1(-3825,4580) -3825,4577 -3760.73,4512.73 U804.7@-3517.45,4512.73
  Bottom Layer w20: D801.1@-3825,4541 v1(-3825,4580)
NetD801_2: D801.2 T800.1 U804.6 | length 369.3
  Top Layer w20: v1@-3730,4582 T800.1@-3730,4670 -3662,4670 -3604.73,4612.73 U804.6@-3517.45,4612.73
  Bottom Layer w20: D801.2@-3730,4535 v1(-3730,4580)
NetJ700_3: J700.3 R700.1 | length 1065.8
  Bottom Layer w30: R700.1@-1342.18,6104.73 -1342.18,6165.18 -1222.62,6284.73 -998.45,6284.73 -904.45,6378.73 -904.45,6511.73 -861.65,6554.53 J700.3@-780.04,6554.53 ; J700.3@-800.05,6574.54 cw(c-848.38,6622.87) -848.38,6554.53 ; -848.38,6554.53 cw(c-848.38,6486.19) -800.05,6534.51 J700.3@-780.04,6554.53 ; -848.38,6554.53 J700.3@-780.04,6554.53
NetJ700_6: J700.6 R706.1 | length 781.4
  Bottom Layer w30: R706.1@-1129.45,6104.73 -1129.45,6169.91 -1076.62,6222.73 -870.62,6222.73 -780.04,6313.32 J700.6@-780.04,6416.73 ; J700.6@-800.05,6396.72 cw(c-848.38,6348.39) -780.04,6348.39 ; -780.04,6348.39 cw(c-711.7,6348.39) -760.02,6396.72 J700.6@-780.04,6416.73 ; -780.04,6348.39 J700.6@-780.04,6416.73
NetJ701_3: J701.3 R701.1 | length 1026.4
  Bottom Layer w30: R701.1@-1772.63,6104.73 -1772.63,6190.72 -1680.62,6282.73 -1472.45,6282.73 -1411.45,6343.73 -1411.45,6514.73 -1371.65,6554.53 J701.3@-1287.04,6554.53 ; J701.3@-1307.05,6574.54 cw(c-1355.38,6622.87) -1355.38,6554.53 ; -1355.38,6554.53 cw(c-1355.38,6486.19) -1307.05,6534.51 J701.3@-1287.04,6554.53 ; -1355.38,6554.53 J701.3@-1287.04,6554.53
NetJ701_6: J701.6 R707.1 | length 687.6
  Bottom Layer w30: R707.1@-1559.9,6104.73 -1559.9,6167.45 -1510.62,6216.73 -1410.62,6216.73 -1287.04,6340.32 J701.6@-1287.04,6416.73 ; J701.6@-1307.05,6396.72 cw(c-1355.38,6348.39) -1287.04,6348.39 ; -1287.04,6348.39 cw(c-1218.7,6348.39) -1267.02,6396.72 J701.6@-1287.04,6416.73 ; -1287.04,6348.39 J701.6@-1287.04,6416.73
NetJ702_3: J702.3 R702.1 | length 946.3
  Bottom Layer w30: R702.1@-2198.08,6104.73 -2198.08,6191.27 -2110.62,6278.73 -1984.62,6278.73 -1918.45,6344.91 -1918.45,6517.73 -1881.65,6554.53 J702.3@-1794.04,6554.53 ; J702.3@-1814.05,6574.54 cw(c-1862.38,6622.87) -1862.38,6554.53 ; -1862.38,6554.53 cw(c-1862.38,6486.19) -1814.05,6534.51 J702.3@-1794.04,6554.53 ; -1862.38,6554.53 J702.3@-1794.04,6554.53
NetJ702_6: J702.6 R708.1 | length 595.2
  Bottom Layer w30: R708.1@-1985.36,6104.73 -1985.36,6154 -1794.04,6345.32 J702.6@-1794.04,6416.73 ; J702.6@-1814.05,6396.72 cw(c-1862.38,6348.39) -1794.04,6348.39 ; -1794.04,6348.39 cw(c-1725.7,6348.39) -1774.02,6396.72 J702.6@-1794.04,6416.73 ; -1794.04,6348.39 J702.6@-1794.04,6416.73
NetJ703_3: J703.3 R703.1 | length 838.4
  Bottom Layer w30: R703.1@-2618.54,6104.73 -2618.54,6168.81 -2425.45,6361.91 -2425.45,6520.73 -2391.65,6554.53 J703.3@-2301.04,6554.53 ; J703.3@-2321.05,6574.54 cw(c-2369.38,6622.87) -2369.38,6554.53 ; -2369.38,6554.53 cw(c-2369.38,6486.19) -2321.05,6534.51 J703.3@-2301.04,6554.53 ; -2369.38,6554.53 J703.3@-2301.04,6554.53
NetJ703_6: J703.6 R709.1 | length 559.4
  Bottom Layer w30: R709.1@-2405.81,6104.73 -2405.81,6207.54 -2301.04,6312.32 J703.6@-2301.04,6416.73 ; J703.6@-2321.05,6396.72 cw(c-2369.38,6348.39) -2301.04,6348.39 ; -2301.04,6348.39 cw(c-2232.7,6348.39) -2281.02,6396.72 J703.6@-2301.04,6416.73 ; -2301.04,6348.39 J703.6@-2301.04,6416.73
NetJ704_3: J704.3 R704.1 | length 801.4
  Bottom Layer w30: R704.1@-3038.99,6104.73 -3038.99,6238.19 -2932.45,6344.73 -2932.45,6518.73 -2896.65,6554.53 J704.3@-2808.04,6554.53 ; J704.3@-2828.05,6574.54 cw(c-2876.38,6622.87) -2876.38,6554.53 ; -2876.38,6554.53 cw(c-2876.38,6486.19) -2828.05,6534.51 J704.3@-2808.04,6554.53 ; -2876.38,6554.53 J704.3@-2808.04,6554.53
NetJ704_6: J704.6 R710.1 | length 525.6
  Bottom Layer w30: R710.1@-2831.27,6104.73 -2831.27,6250.09 -2808.04,6273.32 J704.6@-2808.04,6416.73 ; J704.6@-2828.05,6396.72 cw(c-2876.38,6348.39) -2808.04,6348.39 ; -2808.04,6348.39 cw(c-2739.7,6348.39) -2788.02,6396.72 J704.6@-2808.04,6416.73 ; -2808.04,6348.39 J704.6@-2808.04,6416.73
NetJ705_3: J705.3 R705.1 | length 759.3
  Bottom Layer w30: R705.1@-3454.45,6104.73 -3454.45,6496.73 -3396.65,6554.53 J705.3@-3315.04,6554.53 ; J705.3@-3335.05,6574.54 cw(c-3383.38,6622.87) -3383.38,6554.53 ; -3383.38,6554.53 cw(c-3383.38,6486.19) -3335.05,6534.51 J705.3@-3315.04,6554.53 ; -3383.38,6554.53 J705.3@-3315.04,6554.53
NetJ705_6: J705.6 R711.1 | length 580.7
  Bottom Layer w30: J705.6@-3335.05,6396.72 cw(c-3383.38,6348.39) -3315.04,6348.39 ; J705.6@-3315.04,6416.73 -3315.04,6307.15 ; R711.1@-3246.72,6104.73 -3246.72,6238.83 -3315.04,6307.15 ; -3315.04,6307.15 -3315.04,6348.39 ; -3315.04,6307.15 -3295.02,6396.72 ccw(c-3246.7,6348.39) -3315.04,6348.39
NetQ400_1: Q400.1 R400.2 | length 124.9
  Top Layer w30: R400.2@190.65,3186.64 Q400.1@315.55,3186.64
NetQ401_1: Q401.1 R401.1 | length 124.8
  Top Layer w25: R401.1@190.78,1852.96 Q401.1@315.55,1852.96
NetQ402_1: Q402.1 R402.2 | length 124.3
  Top Layer w30: R402.2@191.21,2742.08 Q402.1@315.55,2742.08
NetQ402_3: Q402.3 Q403.3 R404.2 R405.2 R417.2 | length 56
  Bottom Layer w10: R405.2@40.55,2324.73 R405.2@40.55,2380.73
NetQ403_1: Q403.1 R403.1 | length 126.4
  Top Layer w25: R403.1@191.34,2297.52 R403.1@190.55,2296.73 314.76,2296.73 Q403.1@315.55,2297.52
NetQ404_1: Q404.1 R407.2 | length 106.5
  Top Layer w30: R407.2@214,1394 300.15,1394 Q404.1@314.55,1408.41
NetQ405_1: Q405.1 R408.1 | length 159.6
  Bottom Layer w25: R408.1@240,190 315.55,114.45 Q405.1@315.55,74.73 Q405.1@302.55,74.73
NetQ406_1: Q406.1 R411.2 | length 160.6
  Top Layer w30: R411.2@200,1030 200,996 231.27,964.73 Q406.1@313.67,964.73
NetQ406_3: Q406.3 Q407.3 R413.2 R414.2 R418.2 | length 107.8
  Bottom Layer w10: R413.2@170,752.18 R418.2@170,860
NetQ407_1: Q407.1 R412.1 | length 118.6
  Top Layer w25: R412.1@190.55,524.73 Q407.1@309.11,524.73
NetQ500_1: Q500.1 R500.2 | length 93.6
  Top Layer w25: R500.2@222,6794.53 Q500.1@315.55,6794.53
NetQ501_1: Q501.1 R501.1 | length 111.6
  Top Layer w25: R501.1@204,5460.85 Q501.1@315.55,5460.85
NetQ502_1: Q502.1 R502.2 | length 124.2
  Top Layer w30: R502.2@191.32,6349.97 Q502.1@315.55,6349.97
NetQ502_3: Q502.3 Q503.3 R504.2 R505.2 R517.2 | length 84.1
  Bottom Layer w10: R505.2@29.1,5753.28 R505.2@70.55,5794.73 ; R505.2@52.55,5728.73 R505.2@70.55,5710.73
NetQ503_1: Q503.1 R503.1 | length 129.4
  Top Layer w25: R503.1@190.55,5894.73 201.23,5905.41 Q503.1@315.55,5905.41
NetQ504_1: Q504.1 R507.2 | length 122.8
  Top Layer w30: R507.2@200,4990 224.73,5014.73 Q504.1@312.55,5014.73
NetQ505_1: Q505.1 R508.1 | length 171.2
  Top Layer w25: R508.1@190,3800 305.27,3684.73 Q505.1@313.44,3684.73
NetQ506_1: Q506.1 R511.2 | length 117.4
  Top Layer w30: R511.2@190.55,4574.73 Q506.1@307.99,4574.73
NetQ506_3: Q506.3 Q507.3 R513.2 R514.2 R518.2
NetQ507_1: Q507.1 R512.1 | length 136.9
  Top Layer w25: R512.1@190.55,4162.73 273.67,4162.73 Q507.1@311.67,4124.73
NetR201_1: R201.1 U200.1 | length 146.7
  Top Layer w20: U200.1@-2389.45,1803.53 v1(-2389.45,1876.32)
  Bottom Layer w20: v1(-2389.45,1876.32) -2369.45,1856.32 R201.1@-2369.45,1810.73
NetR202_2: R202.2 U203.10 | length 165.1
  Top Layer w16: U203.10@-2463.45,1130.04 -2463.45,1178.55 -2404.45,1237.55 R202.2@-2404.45,1270.73
NetR205_1: R205.1 U201.1 | length 156.5
  Top Layer w20: U201.1@-2126.95,1803.53 v1(-2126.95,1880.73)
  Bottom Layer w20: v1(-2126.95,1880.73) -2104.45,1858.23 R205.1@-2104.45,1810.73
NetR206_2: R206.2 U203.7 | length 281.6
  Top Layer w16: U203.7@-2313.45,1130.04 -2313.45,1190 -2287.45,1216 -2170,1216 -2139.45,1246.55 R206.2@-2139.45,1270.73
NetR220_2: R220.2 R222.1 U205.4 | length 1686.9
  Top Layer w20: U205.4@-1959.45,1802.94 v1(-1959.45,1870.14)
  Bottom Layer w10: R222.1@-2851.45,2905.73 -2813.72,2868 -2734,2868 -2448,2582 -2448,2184 -2224,1960 -2049.31,1960 v1(-1959.45,1870.14)
  Bottom Layer w20: v1(-1959.45,1870.14) -1944.45,1855.14 R220.2@-1944.45,1810.73
NetR221_1: R221.1 U205.1 | length 168.7
  Top Layer w16: U205.1@-1959.45,1562.94 -1959.45,1640.73
  Bottom Layer w16: R221.1@-1974.45,1570.73 -1974.45,1640.45 v1(-1959.45,1655.45)
NetR301_1: R301.1 U300.1 | length 197.6
  Top Layer w20: U300.1@-2799.45,1729.53 v1(-2799.45,1826.73)
  Bottom Layer w20: v1(-2799.45,1826.73) -2774.45,1801.73 R301.1@-2774.45,1736.73
NetR306_1: R306.1 U302.1 | length 196.9
  Top Layer w20: U302.1@-3141.11,1729.53 v1(-3141.11,1826.73)
  Bottom Layer w20: v1(-3141.11,1826.73) -3117.78,1803.4 R306.1@-3117.78,1736.73
NetR315_1: R315.1 U303.1 | length 159.2
  Top Layer w20: v1(-3482.78,1658) U303.1@-3482.78,1729.53
  Bottom Layer w16: v1(-3482.78,1658) -3461.11,1679.67 R315.1@-3461.11,1736.73
NetR320_1: R320.1 U305.1 | length 195.5
  Top Layer w20: U305.1@-3809.45,1729.53 v1(-3809.45,1826.73)
  Bottom Layer w20: v1(-3809.45,1826.73) -3789.45,1806.73 R320.1@-3789.45,1736.73
NetR600_1: R600.1 R604.1 U600.4 | length 270
  Top Layer w20: R604.1@-1084.45,5011.73 -1084.45,5016.73 R600.1@-1084.45,5126.73 ; R600.1@-1084.45,5118.73 U600.4@-1084.45,5273.73
NetR601_1: R601.1 R605.1 U601.4 | length 270
  Top Layer w20: R605.1@-2360.81,5011.73 -2360.81,5016.73 R601.1@-2360.81,5126.73 ; R601.1@-2360.81,5118.73 U601.4@-2360.81,5273.73
NetR610_1: R610.1 R614.1 U603.4 | length 270
  Top Layer w20: R614.1@-1297.18,5011.73 -1297.18,5016.73 R610.1@-1297.18,5126.73 ; R610.1@-1297.18,5118.73 U603.4@-1297.18,5273.73
NetR611_1: R611.1 R615.1 U604.4 | length 270
  Top Layer w20: R615.1@-2573.54,5011.73 -2573.54,5016.73 R611.1@-2573.54,5126.73 ; R611.1@-2573.54,5118.73 U604.4@-2573.54,5273.73
NetR620_1: R620.1 R624.1 U605.4 | length 270.8
  Top Layer w20: R624.1@-1514.9,5011.73 -1514.9,5016.73 -1514.9,5126.73 R620.1@-1514.08,5126.73 ; R620.1@-1514.9,5118.73 U605.4@-1514.9,5273.73
NetR621_1: R621.1 R625.1 U606.4 | length 270
  Top Layer w20: R625.1@-2786.27,5011.73 -2786.27,5016.73 R621.1@-2786.27,5126.73 ; R621.1@-2786.27,5118.73 U606.4@-2786.27,5273.73
NetR630_1: R630.1 R634.1 U607.4 | length 266.8
  Top Layer w20: R634.1@-1728.62,5016.73 -1727.63,5016.73 -1727.63,5126.73 R630.1@-1726.8,5126.73 ; R630.1@-1727.63,5118.73 U607.4@-1727.63,5273.73
NetR631_1: R631.1 R635.1 U608.4 | length 270
  Top Layer w20: R635.1@-2993.99,5011.73 -2993.99,5016.73 R631.1@-2993.99,5126.73 ; R631.1@-2993.99,5118.73 U608.4@-2993.99,5273.73
NetR640_1: R640.1 R644.1 U610.4 | length 265.8
  Top Layer w20: R644.1@-1940.36,5016.73 -1940.36,5126.73 R640.1@-1939.53,5126.73 ; R640.1@-1940.36,5118.73 U610.4@-1940.36,5273.73
NetR641_1: R641.1 R645.1 U611.4 | length 270
  Top Layer w20: R645.1@-3201.72,5011.73 -3201.72,5016.73 R641.1@-3201.72,5126.73 ; R641.1@-3201.72,5118.73 U611.4@-3201.72,5273.73
NetR650_1: R650.1 R654.1 U612.4 | length 265.8
  Top Layer w20: R654.1@-2153.08,5016.73 -2153.08,5126.73 R650.1@-2152.26,5126.73 ; R650.1@-2153.08,5118.73 U612.4@-2153.08,5273.73
NetR651_1: R651.1 R655.1 U613.4 | length 270
  Top Layer w20: R655.1@-3409.45,5011.73 -3409.45,5016.73 R651.1@-3409.45,5126.73 ; R651.1@-3409.45,5118.73 U613.4@-3409.45,5273.73
NetR813_2: R813.2 Y800.3 | length 81
  Top Layer w10: R813.2@-1476.62,3720.73 Y800.3@-1395.61,3720.73
NetR818_1: R818.1 U802.12 | length 1621.5
  Top Layer w10: U802.12@-3632.96,2100.73 -3670.73,2100.73 -3682,2112 -3682,2142 -3650,2174 -3242,2174 -3144,2272 -3144,2668 -3317.45,2841.45 v1(-3317.45,3060.73)
  Bottom Layer w10: v1(-3317.45,3060.73) -3292.45,3035.73 R818.1@-3292.45,2985.73
NetR901_1: R901.1 U900.2 U900.3 U902.4 | length 523.5
  Bottom Layer w12: U900.2@-3016,3719 -3075,3719 -3100,3744 -3100,3860 R901.1@-3020,3940 U902.4@-2870,3940
  Bottom Layer w20: U900.3@-3016,3669 U900.2@-3016,3719
NetR904_1: R904.1 U902.1 | length 90
  Bottom Layer w10: U902.1@-2630,3940 R904.1@-2630,4030
NetU203_6: U203.6 U205.2 | length 640.9
  Top Layer w12: U203.6@-2263.45,1130.04 -2193.96,1130.04 -1859.45,1464.55 U205.2@-1859.45,1562.94
NetU803_1: U803.1 U803.12 | length 261.4
  Top Layer w10: U803.1@-2160.45,2604.73 -2160.45,2671.55 -2060.45,2771.55 U803.12@-2060.45,2824.73
NetU803_4: U803.4 U803.11 | length 220
  Top Layer w10: U803.4@-2010.45,2604.73 U803.11@-2010.45,2824.73
NetU803_10: U803.10 U804.3 | length 2749.4
  Top Layer w10: U804.3@-3172.45,4612.73 v1@-2814,4612.73 ; v1(-2062,2940) -2004,2940 -1960.45,2896.45 U803.10@-1960.45,2824.73
  Bottom Layer w10: v1(-2814,4612) -2792,4612 -2378,4198 -2378,3856 -2482,3752 -2482,3280 -2336,3134 -2136,3134 -2062,3060 v1(-2062,2940)
NetU803_13: U803.13 U804.2 | length 2587.6
  Top Layer w10: U804.2@-3172.45,4512.73 v1(-2742,4512.73) -2739.31,4512.73 v1@-2738.13,4513.91 ; U803.13@-2110.45,2824.73 v1@-2110.45,2939.73
  Bottom Layer w10: v1(-2742,4512.73) -2404,4174.73 -2404,3866 -2510,3760 -2510,3276 -2346,3112 -2148,3112 -2112,3076 v1(-2112,2940) v1@-2112,2939.73
NetU900_1: U900.1 U901.7 | length 160.7
  Bottom Layer w20: U900.1@-3016,3769 -2967,3769 -2917,3719 U901.7@-2876,3719
NetU900_4: U900.4 U901.6 | length 170.7
  Bottom Layer w20: U900.4@-3016,3619 -2967,3619 -2917,3669 U901.6@-2866,3669
NO1: R800.1 SW800.1 U801.29 | length 1824.1
  Top Layer w10: SW800.1@-2229.45,2314.44 ccw(c-2276.39,2361.39) -2210,2361.39 ccw(c-2143.61,2361.39) SW800.1@-2190.55,2314.44 ; SW800.1@-2222.37,2307.37 ccw(c-2252.25,2337.25) -2210,2337.25 ccw(c-2167.75,2337.25) SW800.1@-2197.63,2307.37 ; SW800.1@-2210,2295 -2210,2426 -2302,2518 -2302,2942 -2172,3072 -1936,3072 -1888.87,3119.13 U801.29@-1888.87,3325.32
  Bottom Layer w10: SW800.1@-2210,2295 R800.1@-2105,2295 ; SW800.1@-2197.63,2282.62 cw(c-2167.75,2252.75) -2167.75,2295 cw(c-2167.75,2337.25) SW800.1@-2197.63,2307.37 ; SW800.1@-2190.55,2275.55 cw(c-2143.61,2228.61) -2143.61,2295 cw(c-2143.61,2361.39) SW800.1@-2190.55,2314.44
NO2: R803.1 SW800.3 U801.30 | length 2094.5
  Top Layer w10: SW800.3@-2210,2095 -2106,2199 -2106,2358 -2276,2528 -2276,2932 -2156,3052 -1924,3052 -1869.18,3106.82 U801.30@-1869.18,3325.32 ; SW800.3@-2210,2112.5 ccw(c-2210,2154.75) -2180.13,2124.87 ccw(c-2150.25,2095) SW800.3@-2192.5,2095 ; SW800.3@-2210,2122.5 ccw(c-2210,2188.89) -2163.05,2141.94 ccw(c-2116.11,2095) SW800.3@-2182.5,2095
  Bottom Layer w10: SW800.3@-2210,2095 R803.1@-2105,2095 ; SW800.3@-2197.63,2082.62 cw(c-2167.75,2052.75) -2167.75,2095 cw(c-2167.75,2137.25) SW800.3@-2197.63,2107.37 ; SW800.3@-2190.55,2075.55 cw(c-2143.61,2028.61) -2143.61,2095 cw(c-2143.61,2161.39) SW800.3@-2190.55,2114.44
NO3: R801.2 SW800.6 U801.32 | length 1887.9
  Top Layer w10: SW800.6@-1932,2278.5 ccw(c-1965,2253.76) -1965,2295 ; SW800.6@-1932,2311.5 cw(c-1965,2336.24) -1965,2295 ; SW800.6@-1924,2284.5 ccw(c-1945,2268.75) -1945,2295 ccw(c-1945,2321.24) SW800.6@-1924,2305.5 ; SW800.6@-1910,2295 -1965,2295 ; U801.32@-1829.81,3325.32 -1829.81,3082.19 -1904,3008 -2128,3008 -2224,2912 -2224,2554 -1965,2295
  Bottom Layer w10: R801.2@-2015,2295 SW800.6@-1910,2295 ; SW800.6@-1929.45,2275.55 ccw(c-1976.39,2228.61) -1976.39,2295 ccw(c-1976.39,2361.39) SW800.6@-1929.45,2314.44 ; SW800.6@-1922.37,2282.62 ccw(c-1952.25,2252.75) -1952.25,2295 ccw(c-1952.25,2337.25) SW800.6@-1922.37,2307.37
NO4: R804.2 SW800.4 U801.31 | length 2116.9
  Top Layer w10: SW800.4@-1937.5,2095 ccw(c-2003.89,2095) -1956.95,2141.94 ccw(c-1910,2188.89) SW800.4@-1910,2122.5 ; SW800.4@-1927.5,2095 ccw(c-1969.75,2095) -1939.87,2124.87 ccw(c-1910,2154.75) SW800.4@-1910,2112.5 ; SW800.4@-1910,2095 -1996,2181 -1996,2288 -2250,2542 -2250,2922 -2142,3030 -1914,3030 -1849.5,3094.5 U801.31@-1849.5,3325.32
  Bottom Layer w10: R804.2@-2015,2095 SW800.4@-1910,2095 ; SW800.4@-1929.45,2075.55 ccw(c-1976.39,2028.61) -1976.39,2095 ccw(c-1976.39,2161.39) SW800.4@-1929.45,2114.44 ; SW800.4@-1922.37,2082.62 ccw(c-1952.25,2052.75) -1952.25,2095 ccw(c-1952.25,2137.25) SW800.4@-1922.37,2107.37
O5: K300.4 U108.14 | length 736.8
  Bottom Layer w20: K300.4@-3824.45,966.73 -3661.18,1130 -3422,1130 -3339.45,1212.55 U108.14@-3339.45,1267.73 ; K300.4@-3824.45,991.73 ccw(c-3824.45,1052.09) -3781.77,1009.41 ccw(c-3739.09,966.73) K300.4@-3799.45,966.73
O6: K301.4 U108.13 | length 480.2
  Bottom Layer w20: K301.4@-3493.11,966.73 -3289.45,1170.4 U108.13@-3289.45,1267.73 ; K301.4@-3493.11,991.73 ccw(c-3493.11,1052.09) -3450.44,1009.41 ccw(c-3407.76,966.73) K301.4@-3468.11,966.73
O7: K302.4 U108.12 | length 423
  Bottom Layer w20: U108.12@-3239.45,1267.73 -3239.45,1155.45 -3173.78,1089.78 K302.4@-3173.78,966.73 ; K302.4@-3191.46,984.41 ccw(c-3234.14,1027.09) -3173.78,1027.09 ccw(c-3113.43,1027.09) K302.4@-3156.1,984.41
O8: K303.4 U108.11 | length 611
  Bottom Layer w20: U108.11@-3189.45,1267.73 -3189.45,1181.45 -2974.73,966.73 K303.4@-2848.45,966.73 ; K303.4@-2866.13,949.05 ccw(c-2908.8,906.38) -2908.8,966.73 ccw(c-2908.8,1027.09) K303.4@-2866.13,984.41
OUT1: J707.1 R208.1 | length 515.9
  Top Layer w30: R208.1@-2524.45,291.73 R208.1@-2522.09,289.37 ; J707.1@-2502.07,86.75 cw(c-2453.75,135.07) -2522.09,135.07 ; -2522.09,135.07 cw(c-2590.43,135.07) -2542.1,86.75 J707.1@-2522.09,66.73 R208.1@-2522.09,289.37 ; -2522.09,135.07 R208.1@-2522.09,289.37
OUT2: J707.3 R209.1 | length 515.9
  Top Layer w30: R209.1@-2224.45,291.73 R209.1@-2222.09,289.37 ; J707.3@-2202.07,86.75 cw(c-2153.75,135.07) -2222.09,135.07 ; -2222.09,135.07 cw(c-2290.43,135.07) -2242.1,86.75 J707.3@-2222.09,66.73 R209.1@-2222.09,289.37 ; -2222.09,135.07 R209.1@-2222.09,289.37
OUT5: J706.1 K300.2 | length 717.7
  Bottom Layer w30: J706.1@-3884.46,86.75 ccw(c-3932.79,135.07) -3864.45,135.07 ccw(c-3796.11,135.07) J706.1@-3844.43,86.75 ; J706.1@-3864.45,66.73 -3864.45,172 -3924.45,232 -3924.45,366.73 K300.2@-3824.45,466.73 ; K300.2@-3844.45,466.73 cw(c-3892.73,466.73) -3858.59,432.59 ; -3858.59,432.59 cw(c-3824.45,398.45) -3824.45,446.73 K300.2@-3824.45,466.73 ; -3858.59,432.59 K300.2@-3824.45,466.73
